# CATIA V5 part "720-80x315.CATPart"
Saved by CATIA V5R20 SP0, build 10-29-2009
Part number: 720-80x315
Definition: NONE
Nomenclature: 720-80x315
Source: Unknown
Description: 720-80x315
Bounding box of the stored display mesh (mm): x 0 to 315, y -40 to 40, z -40 to 40
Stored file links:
  C:\Users\Utente\Desktop\IO LAVORO\3D X SITO CF\X SITO\720\720-80x315.CATPart

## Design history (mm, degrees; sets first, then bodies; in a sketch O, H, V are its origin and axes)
Body1 "720-80x315" (main body)
  Solid1: solid without history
